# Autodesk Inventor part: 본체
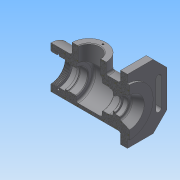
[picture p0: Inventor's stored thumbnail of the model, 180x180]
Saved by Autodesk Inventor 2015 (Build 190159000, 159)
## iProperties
Created: 2017-10
Part Number: 본체
Material: 일반
Document SubType Name: Modeling
Designer: Administrator
Density: 1 g/cm^3
Appearance: 기본값
Author: Administrator
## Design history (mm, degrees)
sketch "스케치1"
  geometry: L1 (-56, 0)-(46, 0); L2 (-56, 0)-(-56, 31); L3 (-56, 31)-(46, 31); L4 (46, 31)-(46, 0); 1 further point
  constraints: 8 end point, 2 perpendicular, 1 horizontal, 1 point on line, 1 vertical
  dimensions: "d0" = 102 distance of L1.start L1.end; "d10" = 62 diameter of L3 L1; "d11" = 56 distance of L1.start point (0, 0)
revolve "회전1" sketch "스케치1" stored, may be unused: angle "d12" = 90 deg
sketch "스케치2"
  geometry: L1 (-58, 47)-(58, 47); L2 (58, 47)-(58, -47); L3 (58, -47)-(-58, -47); L4 (-58, -47)-(-58, 47); C1 r 31 at (0, 0) reference; 2 further points
  constraints: 8 end point, 2 midpoint, 2 parallel, 1 horizontal, 1 horizontal alignment, 1 perpendicular, 1 vertical alignment
  dimensions: "d14" = 94 distance of L1.end L2.end; "d15" = 116 distance of L1.start L1.end
extrude "돌출1" join sketch "스케치2" distance "d16" = 10; taper "d17" = 0 deg
sketch "스케치3"
  geometry: C1 r 35 at (0, 0); 1 further point
  constraints: 1 centre point, 1 coincident
  dimensions: "d18" = 70 diameter of C1
extrude "돌출2" join sketch "스케치3" distance "d19" = 3; taper "d20" = 0 deg
sketch "스케치4"
  geometry: C1 r 25 at (0, 0); 1 further point
  constraints: 1 centre point, 1 coincident
  dimensions: "d21" = 50 diameter of C1
extrude "돌출3" join sketch "스케치4" distance "d22" = 47; taper "d23" = 0 deg
sketch "스케치5"
  geometry: L1 (-56, -31)-(-56, 31) reference; L2 (-56, 0)-(59, 0); L3 (59, -35)-(59, 35) reference; L4 (-47, 0)-(-47, 24); L5 (-47, 24)-(-44, 24); L6 (-44, 24)-(-44, 20); L7 (-44, 20)-(-35, 20); L8 (-35, 20)-(-35, 17.5); L9 (-35, 17.5)-(-31.75, 17.5); L10 (-31.75, 17.5)-(-31.75, 18.5); L11 (-31.75, 18.5)-(-30, 18.5); L12 (-30, 18.5)-(-30, 17.5); L13 (-30, 17.5)-(-19, 17.5); L14 (-19, 17.5)-(-19, 26); L15 (-19, 26)-(19, 26); L16 (19, 26)-(19, 17.5); L17 (19, 17.5)-(30, 17.5); L18 (30, 17.5)-(30, 16.5); L19 (30, 16.5)-(35, 16.5); L20 (35, 16.5)-(35, 10); L21 (35, 10)-(37.7, 10); L22 (37.7, 10)-(37.7, 12.5); L23 (37.7, 12.5)-(44.3, 12.5); L24 (45, 12.904)-(45, 16); L25 (45, 16)-(59, 22); L26 (44.3, 12.5)-(45, 12.904); 1 further point
  constraints: 48 end point, 16 perpendicular, 5 vertical, 2 midpoint, 2 point on line
  dimensions: "d26" = 44 diameter of L25.end L2; "d27" = 32 diameter of L24.end L2; "d28" = 14 horizontal distance of L25.end L24.end; "d29" = 52 diameter of L15 L2; "d30" = 35 diameter of L13 L2; "d31" = 35 diameter of L17 L2; "d32" = 33 diameter of L19 L2; "d33" = 48 diameter of L5 L2; "d34" = 40 diameter of L7 L2; "d35" = 35 diameter of L9 L2; "d36" = 12 distance between parallel lines of L1 L6; "d37" = 3 distance of L4.end L5.end; "d38" = 21 distance between parallel lines of L1 L8; "d39" = 26 distance between parallel lines of L1 L12; "d40" = 60 distance between parallel lines of L18 L12; "d41" = 38 distance of L14.end L15.end; "d42" = 5 distance of L18.end L19.end; "d43" = 1.75 distance of L10.end L11.end; "d44" = 37 diameter of L11 L2; "d45" = 25 diameter of L23 L2; "d46" = 20 diameter of L21 L2; "d47" = 2.7 distance of L20.end L21.end; "d49" = 0.7 distance from line of L23.end L24; "d50" = 30 deg angle of L23 L26; "d51" = 11 distance of L12.end L13.end
revolve "회전2" sketch "스케치5" stored, may be unused: angle "d52" = 90 deg
hole "구멍1" diameter "d55" = 32; stored, may be unused: countersink angle "d59" = 90 deg, drill point angle "d61" = 118 deg; dims "d53" = 10, "d54" = 10, "d56" = 6, "d57" = 4, "d58" = 2, "d60" = 40
hole "구멍2" diameter "d64" = 40.376; stored, may be unused: countersink angle "d68" = 90 deg, drill point angle "d70" = 118 deg; dims "d65" = 11, "d66" = 4, "d67" = 2, "d69" = 11.5, "d73" = 10, "d74" = 10
fillet "모깎기1" dims "d71" = 3
fillet "모깎기2" dims "d72" = 0.3
chamfer "모따기1" distance "d75" = 1; stored, may be unused: second distance "d76" = 2, angle "d77" = 45 deg
chamfer "모따기2" distance "d78" = 20; stored, may be unused: second distance "d79" = 2, angle "d80" = 45 deg
sketch "스케치6"
  geometry: L1 (-50, 20)-(-50, -20); L2 (-42, -20)-(-42, 20); C1 r 35 at (0, 0) reference; A1 r 4 centre (-46, -20) between (-50, -20) and (-42, -20); A2 r 4 centre (-46, 20) between (-42, 20) and (-50, 20)
  constraints: 4 end point, 4 point on circle, 4 tangent, 2 centre point, 1 parallel, 1 vertical
  dimensions: "d81" = 46 horizontal distance of A2.centre C1.centre; "d82" = 40 distance of A1.centre A2.centre; "d83" = 20 vertical distance of C1.centre A1.centre; "d84" = 4 radius of A2
extrude "돌출4" cut sketch "스케치6" stored distance "d85" = 0; taper "d86" = 0 deg
node "작업 평면1"
sketch "스케치7"
  geometry: L1 (-56, -31)-(-56, 31) reference; L2 (25, 47)-(-25, 47) reference; 2 further points
  constraints: 1 other
  dimensions: "d87" = 56 distance from line of point (0, 37) L1; "d88" = 10 distance from line of point (0, 37) L2
feature "엠보싱1" sketch "스케치7" dims "d0" = 102, "d10" = 62, "d11" = 56, "d89" = 0.5, "d90" = 0
fillet "모깎기3" dims "d91" = 3
sketch "스케치8"
  geometry: C1 r 25 at (0, 0) reference; C2 r 17 at (0, 0) reference; A1 r 20.5 centre (0, 0) between (0, 20.5) and (0, -20.5)
  constraints: 2 point on circle, 2 vertical alignment, 1 centre point, 1 coincident
  dimensions: "d92" = 41 diameter of A1
hole "구멍3" sketch "스케치8" at (0, 20.5), (0, -20.5) diameter "d93" = 2.459; stored, may be unused: countersink angle "d97" = 90 deg, drill point angle "d99" = 118 deg; dims "d94" = 6, "d95" = 4, "d96" = 2, "d98" = 8
chamfer "모따기3" distance "d100" = 1; stored, may be unused: second distance "d101" = 2, angle "d102" = 45 deg
fillet "모깎기4" dims "d103" = 3
node "솔리드1"
mirror "대칭1"
